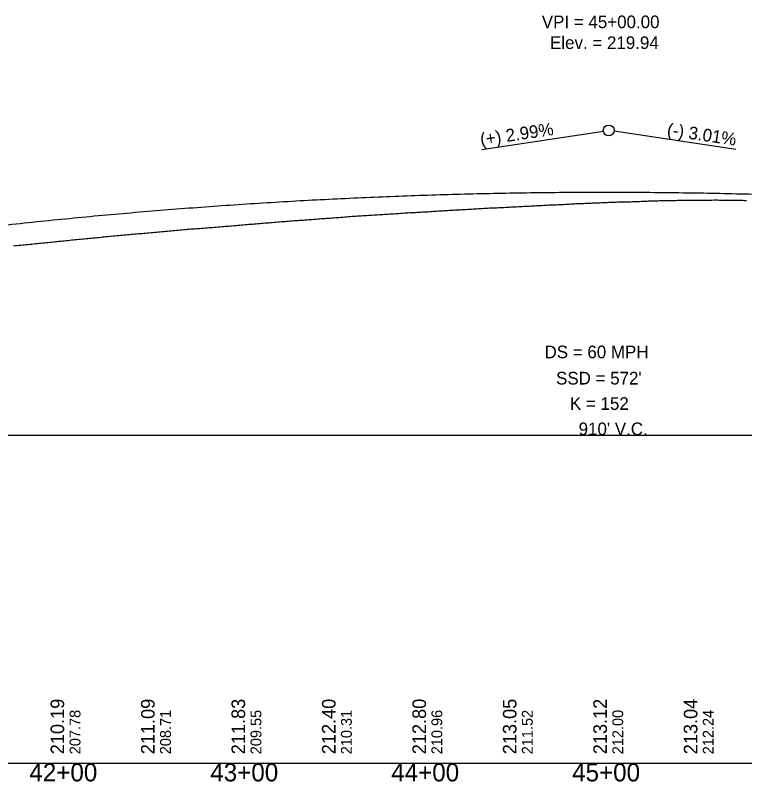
# Model space of a CAD drawing. Extents: x 69 to 2003113, y 512 to 837401.
# Drawn here: x 1891549.5 to 1891952.7, y 820540 to 820963.4 of the extents above; entities that cross this region are included whole.
import ezdxf

# ---------------------------------------------------------------- set-up
doc = ezdxf.new("R2010")
doc.units = 0
for name, color, linetype in [('BR_BORDER LINES', 7, 'Continuous'), ('BR_CENTER LINE BASELINE', 7, 'Continuous'), ('BR_CONCRETE', 7, 'Continuous'), ('BR_GRID DOTS', 7, 'Continuous'), ('BR_GRID LINES', 7, 'Continuous'), ('BR_TEXT', 7, 'Continuous'), ('RD_HC_Points', 7, 'Continuous'), ('RD_SHT_ID', 7, 'Continuous'), ('RD_SHT_IplotShp', 7, 'Continuous')]:
    doc.layers.add(name, color=color, linetype=linetype)

msp = doc.modelspace()

# ---------------------------------------------------------------- linework, layer by layer
at = {"layer": 'BR_BORDER LINES'}
msp.add_line((1889077.53, 820550.13), (1895477.53, 820550.13), dxfattribs=at)
at = {"layer": 'BR_CENTER LINE BASELINE'}
for p, q in [((1891807.31, 820889.35), (1891874.56, 820899.4)), ((1891947.74, 820889.29), (1891880.5, 820899.4))]:
    msp.add_line(p, q, dxfattribs=at)
msp.add_circle((1891877.53, 820899.84), 3, dxfattribs=at)
at = {"layer": 'BR_GRID DOTS'}
msp.add_line((1891422.53, 820731.45), (1892332.53, 820731.45), dxfattribs=at)
at = {"layer": 'BR_GRID LINES'}
msp.add_spline([(1891422.53, 820831.86), (1891440.73, 820834.53), (1891458.93, 820837.08), (1891477.13, 820839.53), (1891495.33, 820841.87), (1891513.53, 820844.1), (1891531.73, 820846.22), (1891549.93, 820848.23), (1891568.13, 820850.13), (1891586.33, 820851.92), (1891604.53, 820853.6), (1891622.73, 820855.17), (1891640.93, 820856.64), (1891659.13, 820857.99), (1891677.33, 820859.24), (1891695.53, 820860.38), (1891713.73, 820861.41), (1891731.93, 820862.32), (1891750.13, 820863.13), (1891768.33, 820863.84), (1891786.53, 820864.43), (1891804.73, 820864.91), (1891822.93, 820865.28), (1891841.13, 820865.55), (1891859.33, 820865.7), (1891877.53, 820865.75), (1891895.73, 820865.69), (1891913.93, 820865.51), (1891932.13, 820865.23), (1891950.33, 820864.84), (1891968.53, 820864.34), (1891986.73, 820863.74), (1892004.93, 820863.02), (1892023.13, 820862.19), (1892041.33, 820861.26), (1892059.53, 820860.21), (1892077.73, 820859.06), (1892095.93, 820857.8), (1892114.13, 820856.42), (1892132.33, 820854.94), (1892150.53, 820853.35), (1892168.73, 820851.65), (1892186.93, 820849.84), (1892205.13, 820847.93), (1892223.33, 820845.9), (1892241.53, 820843.77), (1892259.73, 820841.52), (1892277.93, 820839.17), (1892296.13, 820836.7), (1892314.33, 820834.13), (1892332.53, 820831.45)], degree=3, dxfattribs=at)
at = {"layer": 'BR_TEXT'}
for points in [[(1891804.6, 820856.6), (1891805.6, 820856.67), (1891806.6, 820856.73), (1891807.6, 820856.79), (1891808.6, 820856.84), (1891809.6, 820856.89), (1891810.6, 820856.94), (1891811.6, 820856.98), (1891812.6, 820857.03), (1891813.6, 820857.07), (1891814.6, 820857.11), (1891815.6, 820857.15), (1891816.6, 820857.2), (1891817.6, 820857.24), (1891818.6, 820857.28), (1891819.6, 820857.33), (1891820.6, 820857.38), (1891821.6, 820857.43), (1891822.6, 820857.48), (1891823.6, 820857.54), (1891824.6, 820857.59), (1891825.6, 820857.64), (1891826.6, 820857.69), (1891827.6, 820857.75), (1891828.6, 820857.8), (1891829.6, 820857.85), (1891830.6, 820857.91), (1891831.6, 820857.96), (1891832.6, 820858.02), (1891833.6, 820858.07), (1891834.6, 820858.12), (1891835.6, 820858.18), (1891836.6, 820858.23), (1891837.6, 820858.28), (1891838.6, 820858.33), (1891839.6, 820858.39), (1891840.6, 820858.44), (1891841.6, 820858.49), (1891842.6, 820858.54), (1891843.6, 820858.59), (1891844.6, 820858.64), (1891845.6, 820858.68), (1891846.6, 820858.73), (1891847.6, 820858.77), (1891848.6, 820858.82), (1891849.6, 820858.86), (1891850.6, 820858.91), (1891851.6, 820858.95), (1891852.6, 820859), (1891853.6, 820859.05), (1891854.6, 820859.1), (1891855.6, 820859.15), (1891856.6, 820859.19), (1891857.6, 820859.25), (1891858.6, 820859.32), (1891859.6, 820859.38), (1891860.6, 820859.44), (1891861.6, 820859.47), (1891862.6, 820859.51), (1891863.6, 820859.55), (1891864.6, 820859.59), (1891865.6, 820859.63), (1891866.6, 820859.67), (1891867.6, 820859.71), (1891868.6, 820859.75), (1891869.6, 820859.79), (1891870.6, 820859.83), (1891871.6, 820859.88), (1891872.6, 820859.92), (1891873.6, 820859.96), (1891874.6, 820860), (1891875.6, 820860.05), (1891876.6, 820860.09), (1891877.6, 820860.13), (1891878.6, 820860.17), (1891879.6, 820860.22), (1891880.6, 820860.26), (1891881.6, 820860.29), (1891882.6, 820860.32), (1891883.6, 820860.34), (1891884.6, 820860.36), (1891885.6, 820860.38), (1891886.6, 820860.4), (1891887.6, 820860.42), (1891888.6, 820860.45), (1891889.6, 820860.47), (1891890.6, 820860.49), (1891891.6, 820860.51), (1891892.6, 820860.55), (1891893.6, 820860.6), (1891894.6, 820860.64), (1891895.6, 820860.69), (1891896.6, 820860.74), (1891897.6, 820860.78), (1891898.6, 820860.83), (1891899.6, 820860.88), (1891900.6, 820860.92), (1891901.6, 820860.96), (1891902.6, 820860.99), (1891903.6, 820861.01), (1891904.6, 820861.03)], [(1891904.6, 820861.03), (1891905.6, 820861.05), (1891906.6, 820861.06), (1891907.6, 820861.08), (1891908.6, 820861.09), (1891909.6, 820861.11), (1891910.6, 820861.13), (1891911.6, 820861.15), (1891912.6, 820861.17), (1891913.6, 820861.19), (1891914.6, 820861.2), (1891915.6, 820861.22), (1891916.6, 820861.23), (1891917.6, 820861.24), (1891918.6, 820861.25), (1891919.6, 820861.26), (1891920.6, 820861.27), (1891921.6, 820861.28), (1891922.6, 820861.29), (1891923.6, 820861.31), (1891924.6, 820861.32), (1891925.6, 820861.33), (1891926.6, 820861.34), (1891927.6, 820861.35), (1891928.6, 820861.36), (1891929.6, 820861.36), (1891930.6, 820861.37), (1891931.6, 820861.38), (1891932.6, 820861.39), (1891933.6, 820861.4), (1891934.6, 820861.4), (1891935.6, 820861.41), (1891936.6, 820861.41), (1891937.6, 820861.41), (1891938.6, 820861.4), (1891939.6, 820861.4), (1891940.6, 820861.4), (1891941.6, 820861.39), (1891942.6, 820861.38), (1891943.6, 820861.36), (1891944.6, 820861.35), (1891945.6, 820861.34), (1891946.6, 820861.32), (1891947.6, 820861.31), (1891948.6, 820861.29), (1891949.6, 820861.28), (1891950.6, 820861.26), (1891951.6, 820861.24), (1891952.6, 820861.21), (1891953.6, 820861.18)], [(1891704.6, 820850.06), (1891705.6, 820850.13), (1891706.6, 820850.2), (1891707.6, 820850.26), (1891708.6, 820850.33), (1891709.6, 820850.41), (1891710.6, 820850.48), (1891711.6, 820850.56), (1891712.6, 820850.63), (1891713.6, 820850.71), (1891714.6, 820850.78), (1891715.6, 820850.86), (1891716.6, 820850.93), (1891717.6, 820851.01), (1891718.6, 820851.09), (1891719.6, 820851.16), (1891720.6, 820851.24), (1891721.6, 820851.31), (1891722.6, 820851.38), (1891723.6, 820851.44), (1891724.6, 820851.51), (1891725.6, 820851.57), (1891726.6, 820851.64), (1891727.6, 820851.7), (1891728.6, 820851.77), (1891729.6, 820851.84), (1891730.6, 820851.93), (1891731.6, 820852.07), (1891732.6, 820852.17), (1891733.6, 820852.24), (1891734.6, 820852.31), (1891735.6, 820852.38), (1891736.6, 820852.45), (1891737.6, 820852.52), (1891738.6, 820852.59), (1891739.6, 820852.66), (1891740.6, 820852.73), (1891741.6, 820852.8), (1891742.6, 820852.86), (1891743.6, 820852.91), (1891744.6, 820852.97), (1891745.6, 820853.02), (1891746.6, 820853.08), (1891747.6, 820853.14), (1891748.6, 820853.2), (1891749.6, 820853.26), (1891750.6, 820853.32), (1891751.6, 820853.38), (1891752.6, 820853.45), (1891753.6, 820853.51), (1891754.6, 820853.57), (1891755.6, 820853.63), (1891756.6, 820853.7), (1891757.6, 820853.76), (1891758.6, 820853.83), (1891759.6, 820853.89), (1891760.6, 820853.96), (1891761.6, 820854.03), (1891762.6, 820854.09), (1891763.6, 820854.16), (1891764.6, 820854.23), (1891765.6, 820854.3), (1891766.6, 820854.37), (1891767.6, 820854.43), (1891768.6, 820854.48), (1891769.6, 820854.53), (1891770.6, 820854.58), (1891771.6, 820854.63), (1891772.6, 820854.67), (1891773.6, 820854.72), (1891774.6, 820854.77), (1891775.6, 820854.83), (1891776.6, 820854.89), (1891777.6, 820854.94), (1891778.6, 820855), (1891779.6, 820855.07), (1891780.6, 820855.14), (1891781.6, 820855.21), (1891782.6, 820855.28), (1891783.6, 820855.35), (1891784.6, 820855.41), (1891785.6, 820855.48), (1891786.6, 820855.55), (1891787.6, 820855.61), (1891788.6, 820855.67), (1891789.6, 820855.73), (1891790.6, 820855.78), (1891791.6, 820855.83), (1891792.6, 820855.88), (1891793.6, 820855.93), (1891794.6, 820855.98), (1891795.6, 820856.03), (1891796.6, 820856.08), (1891797.6, 820856.15), (1891798.6, 820856.22), (1891799.6, 820856.29), (1891800.6, 820856.35), (1891801.6, 820856.42), (1891802.6, 820856.48), (1891803.6, 820856.54), (1891804.6, 820856.6)], [(1891604.6, 820841.63), (1891605.6, 820841.73), (1891606.6, 820841.83), (1891607.6, 820841.93), (1891608.6, 820842.04), (1891609.6, 820842.14), (1891610.6, 820842.24), (1891611.6, 820842.33), (1891612.6, 820842.42), (1891613.6, 820842.52), (1891614.6, 820842.6), (1891615.6, 820842.67), (1891616.6, 820842.74), (1891617.6, 820842.81), (1891618.6, 820842.89), (1891619.6, 820842.96), (1891620.6, 820843.03), (1891621.6, 820843.1), (1891622.6, 820843.2), (1891623.6, 820843.3), (1891624.6, 820843.39), (1891625.6, 820843.49), (1891626.6, 820843.58), (1891627.6, 820843.67), (1891628.6, 820843.77), (1891629.6, 820843.86), (1891630.6, 820843.95), (1891631.6, 820844.05), (1891632.6, 820844.14), (1891633.6, 820844.23), (1891634.6, 820844.32), (1891635.6, 820844.42), (1891636.6, 820844.51), (1891637.6, 820844.6), (1891638.6, 820844.7), (1891639.6, 820844.8), (1891640.6, 820844.9), (1891641.6, 820844.99), (1891642.6, 820845.09), (1891643.6, 820845.19), (1891644.6, 820845.26), (1891645.6, 820845.32), (1891646.6, 820845.38), (1891647.6, 820845.44), (1891648.6, 820845.51), (1891649.6, 820845.59), (1891650.6, 820845.66), (1891651.6, 820845.74), (1891652.6, 820845.81), (1891653.6, 820845.89), (1891654.6, 820845.97), (1891655.6, 820846.05), (1891656.6, 820846.13), (1891657.6, 820846.21), (1891658.6, 820846.29), (1891659.6, 820846.38), (1891660.6, 820846.46), (1891661.6, 820846.54), (1891662.6, 820846.63), (1891663.6, 820846.71), (1891664.6, 820846.79), (1891665.6, 820846.87), (1891666.6, 820846.95), (1891667.6, 820847.03), (1891668.6, 820847.11), (1891669.6, 820847.2), (1891670.6, 820847.28), (1891671.6, 820847.37), (1891672.6, 820847.45), (1891673.6, 820847.54), (1891674.6, 820847.62), (1891675.6, 820847.71), (1891676.6, 820847.79), (1891677.6, 820847.87), (1891678.6, 820847.96), (1891679.6, 820848.04), (1891680.6, 820848.13), (1891681.6, 820848.22), (1891682.6, 820848.3), (1891683.6, 820848.39), (1891684.6, 820848.47), (1891685.6, 820848.56), (1891686.6, 820848.64), (1891687.6, 820848.71), (1891688.6, 820848.79), (1891689.6, 820848.86), (1891690.6, 820848.94), (1891691.6, 820849.02), (1891692.6, 820849.11), (1891693.6, 820849.19), (1891694.6, 820849.27), (1891695.6, 820849.35), (1891696.6, 820849.43), (1891697.6, 820849.51), (1891698.6, 820849.6), (1891699.6, 820849.69), (1891700.6, 820849.77), (1891701.6, 820849.85), (1891702.6, 820849.92), (1891703.6, 820849.99), (1891704.6, 820850.06)], [(1891548.6, 820836.07), (1891549.6, 820836.18), (1891550.6, 820836.29), (1891551.6, 820836.4), (1891552.6, 820836.49), (1891553.6, 820836.59), (1891554.6, 820836.69), (1891555.6, 820836.79), (1891556.6, 820836.89), (1891557.6, 820836.99), (1891558.6, 820837.08), (1891559.6, 820837.18), (1891560.6, 820837.28), (1891561.6, 820837.38), (1891562.6, 820837.48), (1891563.6, 820837.58), (1891564.6, 820837.68), (1891565.6, 820837.78), (1891566.6, 820837.89), (1891567.6, 820837.99), (1891568.6, 820838.09), (1891569.6, 820838.19), (1891570.6, 820838.29), (1891571.6, 820838.39), (1891572.6, 820838.49), (1891573.6, 820838.6), (1891574.6, 820838.7), (1891575.6, 820838.8), (1891576.6, 820838.9), (1891577.6, 820839.01), (1891578.6, 820839.11), (1891579.6, 820839.2), (1891580.6, 820839.3), (1891581.6, 820839.4), (1891582.6, 820839.49), (1891583.6, 820839.59), (1891584.6, 820839.68), (1891585.6, 820839.78), (1891586.6, 820839.87), (1891587.6, 820839.96), (1891588.6, 820840.06), (1891589.6, 820840.15), (1891590.6, 820840.25), (1891591.6, 820840.35), (1891592.6, 820840.46), (1891593.6, 820840.56), (1891594.6, 820840.66), (1891595.6, 820840.76), (1891596.6, 820840.86), (1891597.6, 820840.96), (1891598.6, 820841.07), (1891599.6, 820841.17), (1891600.6, 820841.25), (1891601.6, 820841.34), (1891602.6, 820841.43), (1891603.6, 820841.52), (1891604.6, 820841.63)]]:
    msp.add_lwpolyline(points, dxfattribs=at)

# ---------------------------------------------------------------- texts
at = {"layer": 'BR_CENTER LINE BASELINE'}
for s, rotation, p in [('(+) 2.99%', 8.4971, (1891807.01, 820891.33)), ('(-) 3.01%', 351.4519, (1891909.43, 820897.07))]:
    msp.add_text(s, height=7, rotation=rotation, dxfattribs=at).set_placement(p)
at = {"layer": 'BR_CONCRETE'}
for s, p in [('207.78', (1891585.53, 820555.13)), ('208.71', (1891635.53, 820555.13)), ('209.55', (1891685.53, 820555.13)), ('210.31', (1891735.53, 820555.13)), ('210.96', (1891785.53, 820555.13)), ('211.52', (1891835.53, 820555.13)), ('212.00', (1891885.53, 820555.13)), ('212.24', (1891935.53, 820555.13))]:
    msp.add_text(s, height=6, rotation=90, dxfattribs=at).set_placement(p)
at = {"layer": 'BR_GRID DOTS'}
for s, p in [('DS = 60 MPH', (1891842.05, 820773.94)), ("SSD = 572'", (1891848.41, 820759.45)), ('K = 152', (1891856.07, 820745.45)), ("910' V.C.", (1891860.89, 820731.45))]:
    msp.add_text(s, height=7, dxfattribs=at).set_placement(p)
at = {"layer": 'RD_HC_Points'}
for s, p in [('210.19', (1891576.53, 820555.13)), ('211.09', (1891626.53, 820555.13)), ('211.83', (1891676.53, 820555.13)), ('212.40', (1891726.53, 820555.13)), ('212.80', (1891776.53, 820555.13)), ('213.05', (1891826.53, 820555.13)), ('213.12', (1891876.53, 820555.13)), ('213.04', (1891926.53, 820555.13))]:
    msp.add_text(s, height=7.5, rotation=90, dxfattribs=at).set_placement(p)
at = {"layer": 'RD_SHT_ID'}
for s, p in [('42+00', (1891557.29, 820540.13)), ('43+00', (1891657.29, 820540.13)), ('44+00', (1891757.29, 820540.13)), ('45+00', (1891857.29, 820540.13))]:
    msp.add_text(s, height=10, dxfattribs=at).set_placement(p)
at = {"layer": 'RD_SHT_IplotShp'}
for s, p in [('VPI = 45+00.00', (1891840.55, 820956.34)), ('Elev. = 219.94', (1891845.08, 820944.84))]:
    msp.add_text(s, height=7, dxfattribs=at).set_placement(p)

doc.saveas('drawing.dxf')
